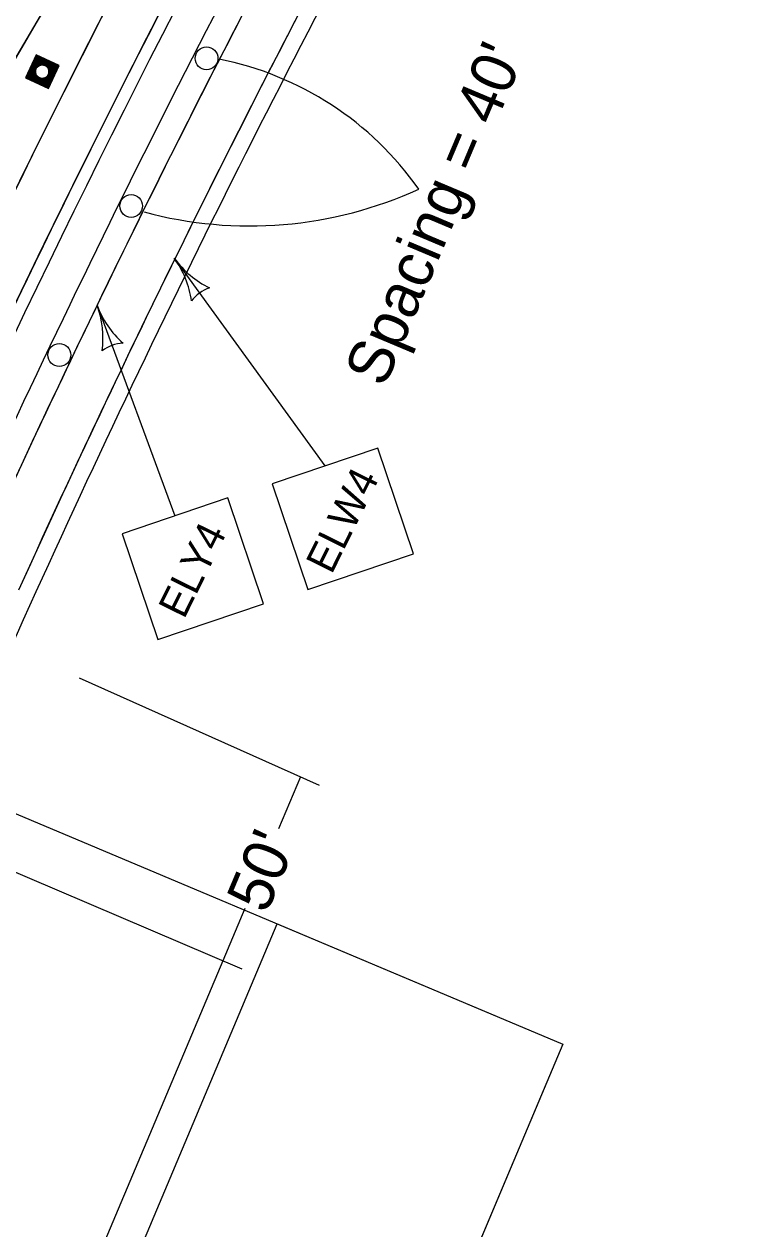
# Model space of a CAD drawing. Extents: x 14104283 to 14128447, y 8633203 to 8671666.
# Drawn here: x 14119000.1 to 14119176.9, y 8668365.7 to 8668657.2 of the extents above; entities that cross this region are included whole.
import ezdxf

# ---------------------------------------------------------------- set-up
doc = ezdxf.new("R2010")
doc.units = 0
for name, color, linetype in [('Cell', 7, 'Continuous'), ('dsnCellElements', 7, 'Continuous'), ('dsnNonPlotable', 7, 'Continuous'), ('dsnPaintPlaceEdgeLineLeftYellow', 7, 'Continuous'), ('dsnPaintPlaceEdgeLineRightWhite', 7, 'Continuous'), ('dsnShadingPaved', 7, 'Continuous'), ('dsnStdLabel', 7, 'Continuous'), ('dsnStgShadingPrevPav', 7, 'Continuous'), ('dsnStgShadingPropPav', 7, 'Continuous'), ('dsnTapeExistingChannelizingLaneWhite', 7, 'Continuous'), ('dsnTapeExistingChannelizingLaneYellow', 7, 'Continuous'), ('dsnTapeRemoveChannelizingWhite', 7, 'Continuous'), ('dsnTapeRemoveChannelizingYellow', 7, 'Continuous'), ('dsnTextOverlapEven', 7, 'Continuous')]:
    doc.layers.add(name, color=color, linetype=linetype)

msp = doc.modelspace()

# ---------------------------------------------------------------- linework, layer by layer
at = {"layer": 'Cell'}
for centre in [(14119044.23, 8668648.9), (14119026, 8668613.18), (14119008.62, 8668577.13)]:
    msp.add_circle(centre, 2.75, dxfattribs=at)
at = {"layer": 'dsnCellElements'}
msp.add_circle((14119004.47, 8668645.68), 1.65, dxfattribs=at)
at = {"layer": 'dsnNonPlotable'}
msp.add_lwpolyline([(14118056.48, 8667161.91), (14118665.06, 8668606.45), (14119130.44, 8668410.38), (14118521.87, 8666965.84)], close=True, dxfattribs=at)
at = {"layer": 'dsnPaintPlaceEdgeLineLeftYellow'}
msp.add_arc((14121592.11, 8667345.68), 2858.95, 150.1629, 155.63386, dxfattribs=at)
at = {"layer": 'dsnPaintPlaceEdgeLineRightWhite'}
msp.add_arc((14121592.11, 8667345.68), 2846.95, 150.15883, 155.63386, dxfattribs=at)
at = {"layer": 'dsnShadingPaved'}
for centre, radius, start, end in [((14121955.85, 8666791.92), 3512, 144.95493, 152.69211), ((14121955.85, 8666791.92), 3500, 144.95493, 152.69211), ((14121592.11, 8667345.68), 2858.95, 151.16499, 155.63386), ((14121592.11, 8667345.68), 2846.95, 151.16499, 155.63386)]:
    msp.add_arc(centre, radius, start, end, dxfattribs=at)
at = {"layer": 'dsnStdLabel'}
for p, q in [((14119036.43, 8668600.52), (14119072.88, 8668550.29)), ((14119017.76, 8668589.18), (14119036.57, 8668538.21)), ((14119013.41, 8668499), (14119071.5, 8668473.02)), ((14119066.93, 8668475.06), (14119061.62, 8668462.46)), ((14118993.28, 8668453.99), (14119052.79, 8668428.61)), ((14119053.52, 8668443.22), (14119048.19, 8668430.57)), ((14119048.19, 8668430.57), (14118955.01, 8668209.4))]:
    msp.add_line(p, q, dxfattribs=at)
for points in [[(14119005.96, 8668641.61), (14119008.54, 8668647.17), (14119002.98, 8668649.74), (14119000.4, 8668644.19), (14119005.96, 8668641.61)], [(14119005.96, 8668641.61), (14119008.53, 8668647.17), (14119002.98, 8668649.74), (14119000.41, 8668644.19), (14119005.96, 8668641.62)], [(14119005.96, 8668641.61), (14119008.53, 8668647.17), (14119002.98, 8668649.74), (14119000.41, 8668644.19), (14119005.97, 8668641.62)], [(14119005.99, 8668641.75), (14119008.48, 8668647.15), (14119003, 8668649.69), (14119000.46, 8668644.2), (14119005.98, 8668641.65)], [(14119005.97, 8668641.8), (14119008.44, 8668647.14), (14119003.01, 8668649.65), (14119000.5, 8668644.22), (14119005.99, 8668641.68)], [(14119005.95, 8668641.84), (14119008.4, 8668647.12), (14119003.03, 8668649.6), (14119000.54, 8668644.24), (14119006.01, 8668641.71)], [(14119005.94, 8668641.89), (14119008.35, 8668647.1), (14119003.05, 8668649.56), (14119000.59, 8668644.25), (14119005.99, 8668641.75)], [(14119005.92, 8668641.93), (14119008.31, 8668647.09), (14119003.06, 8668649.52), (14119000.63, 8668644.27), (14119005.97, 8668641.8)], [(14119005.9, 8668641.97), (14119008.26, 8668647.07), (14119003.08, 8668649.47), (14119000.68, 8668644.29), (14119005.95, 8668641.84)], [(14119005.89, 8668642.02), (14119008.22, 8668647.06), (14119003.09, 8668649.43), (14119000.72, 8668644.3), (14119005.94, 8668641.89)], [(14119005.87, 8668642.06), (14119008.18, 8668647.04), (14119003.11, 8668649.39), (14119000.76, 8668644.32), (14119005.92, 8668641.93)], [(14119005.86, 8668642.1), (14119008.13, 8668647.02), (14119003.13, 8668649.34), (14119000.81, 8668644.33), (14119005.9, 8668641.97)], [(14119005.84, 8668642.15), (14119008.09, 8668647.01), (14119003.14, 8668649.3), (14119000.85, 8668644.35), (14119005.89, 8668642.02)], [(14119005.82, 8668642.19), (14119008.05, 8668646.99), (14119003.16, 8668649.25), (14119000.89, 8668644.37), (14119005.87, 8668642.06)], [(14119005.81, 8668642.24), (14119008, 8668646.97), (14119003.17, 8668649.21), (14119000.94, 8668644.38), (14119005.86, 8668642.1)], [(14119005.79, 8668642.28), (14119007.96, 8668646.96), (14119003.19, 8668649.17), (14119000.98, 8668644.4), (14119005.84, 8668642.15)], [(14119005.78, 8668642.32), (14119007.91, 8668646.94), (14119003.21, 8668649.12), (14119001.03, 8668644.41), (14119005.82, 8668642.19)], [(14119005.76, 8668642.37), (14119007.87, 8668646.93), (14119003.22, 8668649.08), (14119001.07, 8668644.43), (14119005.81, 8668642.24)], [(14119005.74, 8668642.41), (14119007.83, 8668646.91), (14119003.24, 8668649.03), (14119001.11, 8668644.45), (14119005.79, 8668642.28)], [(14119005.73, 8668642.46), (14119007.78, 8668646.89), (14119003.25, 8668648.99), (14119001.16, 8668644.46), (14119005.78, 8668642.32)], [(14119005.71, 8668642.5), (14119007.74, 8668646.88), (14119003.27, 8668648.95), (14119001.2, 8668644.48), (14119005.76, 8668642.37)], [(14119005.7, 8668642.54), (14119007.7, 8668646.86), (14119003.29, 8668648.9), (14119001.25, 8668644.49), (14119005.74, 8668642.41)], [(14119005.68, 8668642.59), (14119007.65, 8668646.85), (14119003.3, 8668648.86), (14119001.29, 8668644.51), (14119005.73, 8668642.46)], [(14119005.66, 8668642.63), (14119007.61, 8668646.83), (14119003.32, 8668648.82), (14119001.33, 8668644.53), (14119005.71, 8668642.5)], [(14119005.65, 8668642.67), (14119007.56, 8668646.81), (14119003.33, 8668648.77), (14119001.38, 8668644.54), (14119005.7, 8668642.54)], [(14119005.63, 8668642.72), (14119007.52, 8668646.8), (14119003.35, 8668648.73), (14119001.42, 8668644.56), (14119005.68, 8668642.59)], [(14119005.62, 8668642.76), (14119007.48, 8668646.78), (14119003.37, 8668648.68), (14119001.46, 8668644.57), (14119005.66, 8668642.63)], [(14119005.6, 8668642.81), (14119007.43, 8668646.77), (14119003.38, 8668648.64), (14119001.51, 8668644.59), (14119005.65, 8668642.67)], [(14119005.58, 8668642.85), (14119007.39, 8668646.75), (14119003.4, 8668648.6), (14119001.55, 8668644.61), (14119005.63, 8668642.72)], [(14119005.57, 8668642.89), (14119007.34, 8668646.73), (14119003.42, 8668648.55), (14119001.6, 8668644.62), (14119005.62, 8668642.76)], [(14119005.55, 8668642.94), (14119007.3, 8668646.72), (14119003.43, 8668648.51), (14119001.64, 8668644.64), (14119005.6, 8668642.81)], [(14119005.54, 8668642.98), (14119007.26, 8668646.7), (14119003.45, 8668648.47), (14119001.68, 8668644.66), (14119005.58, 8668642.85)], [(14119005.52, 8668643.02), (14119007.21, 8668646.69), (14119003.46, 8668648.42), (14119001.73, 8668644.67), (14119005.57, 8668642.89)], [(14119005.5, 8668643.07), (14119007.17, 8668646.67), (14119003.48, 8668648.38), (14119001.77, 8668644.69), (14119005.55, 8668642.94)], [(14119005.49, 8668643.11), (14119007.13, 8668646.65), (14119003.5, 8668648.33), (14119001.81, 8668644.7), (14119005.54, 8668642.98)], [(14119005.47, 8668643.16), (14119007.08, 8668646.64), (14119003.51, 8668648.29), (14119001.86, 8668644.72), (14119005.52, 8668643.02)], [(14119005.45, 8668643.2), (14119007.04, 8668646.62), (14119003.53, 8668648.25), (14119001.9, 8668644.74), (14119005.5, 8668643.07)], [(14119005.44, 8668643.24), (14119006.99, 8668646.6), (14119003.54, 8668648.2), (14119001.95, 8668644.75), (14119005.49, 8668643.11)], [(14119005.42, 8668643.29), (14119006.95, 8668646.59), (14119003.56, 8668648.16), (14119001.99, 8668644.77), (14119005.47, 8668643.16)], [(14119005.41, 8668643.33), (14119006.91, 8668646.57), (14119003.58, 8668648.11), (14119002.03, 8668644.78), (14119005.45, 8668643.2)], [(14119005.39, 8668643.38), (14119006.86, 8668646.56), (14119003.59, 8668648.07), (14119002.08, 8668644.8), (14119005.44, 8668643.24)], [(14119005.37, 8668643.42), (14119006.82, 8668646.54), (14119003.61, 8668648.03), (14119002.12, 8668644.82), (14119005.42, 8668643.29)], [(14119005.36, 8668643.46), (14119006.78, 8668646.52), (14119003.62, 8668647.98), (14119002.17, 8668644.83), (14119005.41, 8668643.33)], [(14119005.34, 8668643.51), (14119006.73, 8668646.51), (14119003.64, 8668647.94), (14119002.21, 8668644.85), (14119005.39, 8668643.38)], [(14119005.33, 8668643.55), (14119006.69, 8668646.49), (14119003.66, 8668647.9), (14119002.25, 8668644.86), (14119005.37, 8668643.42)], [(14119005.31, 8668643.59), (14119006.64, 8668646.48), (14119003.67, 8668647.85), (14119002.3, 8668644.88), (14119005.36, 8668643.46)], [(14119002.89, 8668646.07), (14119002.34, 8668644.9), (14119003.52, 8668644.35)], [(14119002.86, 8668645.93), (14119002.38, 8668644.91), (14119003.4, 8668644.44)], [(14119002.84, 8668645.83), (14119002.43, 8668644.93), (14119003.33, 8668644.51)], [(14119002.84, 8668645.73), (14119002.47, 8668644.94), (14119003.26, 8668644.58)], [(14119004.86, 8668647.26), (14119003.69, 8668647.81), (14119003.14, 8668646.63)], [(14119004.73, 8668647.29), (14119003.7, 8668647.76), (14119003.23, 8668646.74)], [(14119004.62, 8668647.31), (14119003.72, 8668647.72), (14119003.31, 8668646.82)], [(14119004.53, 8668647.31), (14119003.74, 8668647.68), (14119003.37, 8668646.89)], [(14119004.45, 8668647.31), (14119003.75, 8668647.63), (14119003.43, 8668646.94)], [(14119004.37, 8668647.31), (14119003.77, 8668647.59), (14119003.49, 8668646.98)], [(14119004.31, 8668647.3), (14119003.79, 8668647.55), (14119003.54, 8668647.02)], [(14119004.24, 8668647.3), (14119003.8, 8668647.5), (14119003.6, 8668647.06)], [(14119004.19, 8668647.29), (14119003.82, 8668647.46), (14119003.65, 8668647.09)], [(14119004.13, 8668647.28), (14119003.83, 8668647.41), (14119003.7, 8668647.12)], [(14119004.08, 8668647.26), (14119003.85, 8668647.37), (14119003.74, 8668647.14)], [(14119004.03, 8668647.25), (14119003.87, 8668647.33), (14119003.79, 8668647.16)], [(14119003.98, 8668647.24), (14119003.88, 8668647.28), (14119003.84, 8668647.18)], [(14119003.93, 8668647.22), (14119003.9, 8668647.24), (14119003.88, 8668647.2)], [(14119006.06, 8668645.28), (14119006.6, 8668646.46), (14119005.42, 8668647)], [(14119006.08, 8668645.42), (14119006.56, 8668646.44), (14119005.54, 8668646.92)], [(14119006.1, 8668645.53), (14119006.51, 8668646.43), (14119005.62, 8668646.84)], [(14119006.1, 8668645.62), (14119006.47, 8668646.41), (14119005.68, 8668646.78)], [(14119006.1, 8668645.7), (14119006.42, 8668646.4), (14119005.73, 8668646.72)], [(14119006.1, 8668645.77), (14119006.38, 8668646.38), (14119005.78, 8668646.66)], [(14119006.1, 8668645.84), (14119006.34, 8668646.36), (14119005.82, 8668646.61)], [(14119006.09, 8668645.9), (14119006.29, 8668646.35), (14119005.85, 8668646.55)], [(14119006.08, 8668645.96), (14119006.25, 8668646.33), (14119005.88, 8668646.5)], [(14119006.07, 8668646.02), (14119006.21, 8668646.32), (14119005.91, 8668646.45)], [(14119006.06, 8668646.07), (14119006.16, 8668646.3), (14119005.93, 8668646.41)], [(14119006.04, 8668646.12), (14119006.12, 8668646.28), (14119005.96, 8668646.36)], [(14119006.03, 8668646.17), (14119006.07, 8668646.27), (14119005.98, 8668646.31)], [(14119006.01, 8668646.21), (14119006.03, 8668646.25), (14119005.99, 8668646.27)], [(14119002.84, 8668645.65), (14119002.52, 8668644.96), (14119003.21, 8668644.64)], [(14119002.84, 8668645.58), (14119002.56, 8668644.98), (14119003.16, 8668644.7)], [(14119002.85, 8668645.51), (14119002.6, 8668644.99), (14119003.13, 8668644.75)], [(14119002.85, 8668645.45), (14119002.65, 8668645.01), (14119003.09, 8668644.8)], [(14119002.86, 8668645.39), (14119002.69, 8668645.03), (14119003.06, 8668644.85)], [(14119002.87, 8668645.34), (14119002.74, 8668645.04), (14119003.03, 8668644.9)], [(14119002.88, 8668645.29), (14119002.78, 8668645.06), (14119003.01, 8668644.95)], [(14119002.9, 8668645.24), (14119002.82, 8668645.07), (14119002.99, 8668645)], [(14119002.91, 8668645.19), (14119002.87, 8668645.09), (14119002.97, 8668645.04)], [(14119002.93, 8668645.14), (14119002.91, 8668645.11), (14119002.95, 8668645.09)], [(14119004.08, 8668644.09), (14119005.34, 8668643.51)], [(14119004.22, 8668644.06), (14119005.33, 8668643.55)], [(14119004.32, 8668644.05), (14119005.31, 8668643.59)], [(14119004.41, 8668644.05), (14119005.29, 8668643.64)], [(14119004.49, 8668644.04), (14119005.28, 8668643.68)], [(14119004.57, 8668644.05), (14119005.26, 8668643.73)], [(14119004.63, 8668644.05), (14119005.25, 8668643.77)], [(14119004.7, 8668644.06), (14119005.23, 8668643.81)], [(14119004.75, 8668644.07), (14119005.21, 8668643.86)], [(14119004.81, 8668644.08), (14119005.2, 8668643.9)], [(14119004.86, 8668644.09), (14119005.18, 8668643.94)], [(14119004.91, 8668644.11), (14119005.17, 8668643.99)], [(14119004.96, 8668644.12), (14119005.15, 8668644.03)], [(14119005.01, 8668644.14), (14119005.13, 8668644.08)], [(14119005.13, 8668644.08), (14119005.2, 8668644.22)], [(14119005.15, 8668644.03), (14119005.25, 8668644.24)], [(14119005.17, 8668643.99), (14119005.29, 8668644.27)], [(14119005.18, 8668643.94), (14119005.34, 8668644.3)], [(14119005.2, 8668643.9), (14119005.4, 8668644.33)], [(14119005.21, 8668643.86), (14119005.45, 8668644.37)], [(14119005.23, 8668643.81), (14119005.51, 8668644.42)], [(14119005.25, 8668643.77), (14119005.57, 8668644.47)], [(14119005.26, 8668643.73), (14119005.64, 8668644.53)], [(14119005.28, 8668643.68), (14119005.71, 8668644.61)], [(14119005.29, 8668643.64), (14119005.8, 8668644.72)]]:
    msp.add_lwpolyline(points, dxfattribs=at)
for points in [[(14119068.74, 8668520.39), (14119094.32, 8668529.04), (14119085.67, 8668554.62), (14119060.09, 8668545.96)], [(14119032.43, 8668508.3), (14119058.01, 8668516.96), (14119049.35, 8668542.53), (14119023.78, 8668533.88)]]:
    msp.add_lwpolyline(points, close=True, dxfattribs=at)
for centre, radius, start, end in [((14119032.2, 8668572.76), 77.42, 35.0866, 78.7931), ((14119054.69, 8668706.47), 98.12, 254.8963, 294.6127), ((14119017.86, 8668587.04), 22.95, 7.893, 35.9643), ((14119055.01, 8668614), 22.95, 215.9642, 244.0354), ((14119047.73, 8668584.95), 8.86, 108.23, 143.6985), ((14118996.23, 8668581.24), 22.95, 352.1764, 20.2478), ((14119039.29, 8668597.12), 22.95, 200.2476, 228.3189), ((14119024.42, 8668571.13), 8.86, 92.5134, 127.9819)]:
    msp.add_arc(centre, radius, start, end, dxfattribs=at)
at = {"layer": 'dsnStgShadingPrevPav'}
for centre, radius, start, end in [((14123732.96, 8665874.38), 5512, 146.42562, 157.1633), ((14123732.59, 8665873.82), 5512, 146.50213, 150.36196), ((14123732.96, 8665874.38), 5488, 146.42119, 157.1633), ((14121592.11, 8667345.68), 2888.95, 147.23666, 156.23389), ((14123732.85, 8665874.2), 5488.01, 146.41277, 150.66874), ((14121592.11, 8667345.68), 2888.95, 147.23666, 155.3184), ((14121592.11, 8667345.68), 2876.95, 147.24009, 156.23389), ((14121592.11, 8667345.68), 2876.95, 147.18034, 155.90343), ((14121592.11, 8667345.68), 2873.95, 147.18114, 155.90343), ((14121592.11, 8667345.68), 2864.95, 151.16499, 155.90343), ((14121592.11, 8667345.68), 2842.95, 151.16499, 155.90343)]:
    msp.add_arc(centre, radius, start, end, dxfattribs=at)
at = {"layer": 'dsnStgShadingPropPav'}
for radius, start in [(2864.95, 151.16499), (2876.95, 152.63404)]:
    msp.add_arc((14121592.11, 8667345.68), radius, start, 155.90343, dxfattribs=at)
at = {"layer": 'dsnTapeExistingChannelizingLaneWhite'}
msp.add_arc((14121955.85, 8666791.92), 3512, 145.38458, 147.96378, dxfattribs=at)
at = {"layer": 'dsnTapeExistingChannelizingLaneYellow'}
msp.add_arc((14121955.85, 8666791.92), 3500, 144.95493, 149.50762, dxfattribs=at)
at = {"layer": 'dsnTapeRemoveChannelizingWhite'}
msp.add_arc((14121592.11, 8667345.68), 2876.95, 151.24538, 156.90337, dxfattribs=at)
at = {"layer": 'dsnTapeRemoveChannelizingYellow'}
msp.add_arc((14121592.11, 8667345.68), 2888.95, 151.24538, 156.90337, dxfattribs=at)
at = {"layer": 'dsnTextOverlapEven'}
for points in [[(14119130.44, 8668410.38), (14119053.07, 8668226.74), (14118983.96, 8668255.86), (14119061.32, 8668439.5)], [(14118983.96, 8668255.86), (14119061.32, 8668439.5), (14119130.44, 8668410.38), (14119053.07, 8668226.74)]]:
    msp.add_lwpolyline(points, close=True, dxfattribs=at)

# ---------------------------------------------------------------- texts
at = {"layer": 'dsnStdLabel'}
for s, height, rotation, p in [("Spacing = 40'", 10.8, 67.1547, (14119087.26, 8668568.97)), ('ELW4', 7.2, 63.6912, (14119074.47, 8668523.85)), ('ELY4', 7.2, 63.6912, (14119038.77, 8668513.01)), ("50'", 10.8, 67.1547, (14119058.72, 8668441.66))]:
    msp.add_text(s, height=height, rotation=rotation, dxfattribs=at).set_placement(p)

doc.saveas('drawing.dxf')
